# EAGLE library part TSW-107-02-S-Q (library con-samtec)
THROUGH-HOLE .025" SQ POST HEADER Source: Samtec TSW.pdf
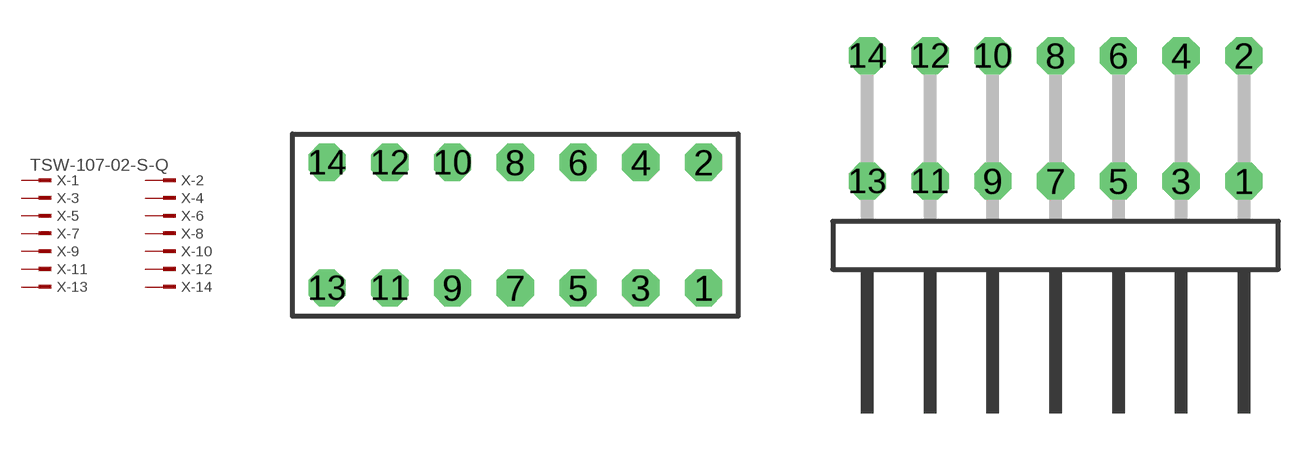
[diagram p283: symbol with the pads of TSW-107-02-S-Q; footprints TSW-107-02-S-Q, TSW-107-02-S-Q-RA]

Designator prefix X; gates -1=MPINV -2=MPIN -3=MPIN -4=MPIN -5=MPIN -6=MPIN -7=MPIN -8=MPIN -9=MPIN -10=MPIN -11=MPIN -12=MPIN -13=MPIN -14=MPIN

## TSW-107-02-S-Q (OC_FARNELL: unknown; OC_NEWARK: unknown)  [TSW-107-02-S-Q]
1  -1:1  pas
2  -2:1  pas
3  -3:1  pas
4  -4:1  pas
5  -5:1  pas
6  -6:1  pas
7  -7:1  pas
8  -8:1  pas
9  -9:1  pas
10  -10:1  pas
11  -11:1  pas
12  -12:1  pas
13  -13:1  pas
14  -14:1  pas

## TSW-107-02-S-Q-RA (OC_FARNELL: unknown; OC_NEWARK: unknown)  [TSW-107-02-S-Q-RA]
Pads as for TSW-107-02-S-Q

## Footprint TSW-107-02-S-Q (pad centres in mm)
THROUGH-HOLE .025" SQ POST HEADER Source: Samtec TSW.pdf
drill 1 pad 1.5 octagon: 1 7.62,-2.54; 2 7.62,2.54; 3 5.08,-2.54; 4 5.08,2.54; 5 2.54,-2.54; 6 2.54,2.54; 7 0,-2.54; 8 0,2.54; 9 -2.54,-2.54; 10 -2.54,2.54; 11 -5.08,-2.54; 12 -5.08,2.54; 13 -7.62,-2.54; 14 -7.62,2.54

## Footprint TSW-107-02-S-Q-RA (pad centres in mm)
THROUGH-HOLE .025" SQ POST HEADER Source: Samtec TSW.pdf
drill 1 pad 1.5 octagon: 1 7.62,1.524; 2 7.62,6.604; 3 5.08,1.524; 4 5.08,6.604; 5 2.54,1.524; 6 2.54,6.604; 7 0,1.524; 8 0,6.604; 9 -2.54,1.524; 10 -2.54,6.604; 11 -5.08,1.524; 12 -5.08,6.604; 13 -7.62,1.524; 14 -7.62,6.604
